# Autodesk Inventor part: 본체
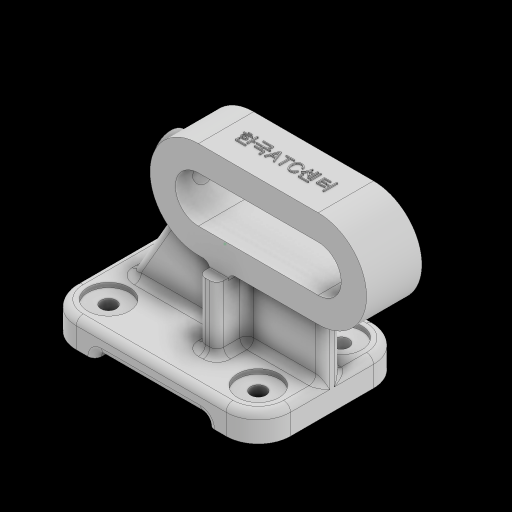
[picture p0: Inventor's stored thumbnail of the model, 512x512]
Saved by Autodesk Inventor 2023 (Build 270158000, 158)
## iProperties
Created: 2025-01
Part Number: 본체
Material: 일반
Document SubType Name: Modeling
Designer: 강의실01
Density: 1 g/cm^3
Appearance: 기본값
Author: 강의실01
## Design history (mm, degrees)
sketch "스케치1"
  geometry: L1 (46.5, -32)-(-46.5, -32); L2 (-46.5, -32)-(-46.5, 32); L3 (-46.5, 32)-(46.5, 32); L4 (46.5, 32)-(46.5, -32); L5 (46.5, -32)-(-46.5, 32); L6 (-46.5, -32)-(46.5, 32); 1 further point
  constraints: 12 end point, 2 midpoint, 2 parallel, 1 horizontal, 1 perpendicular
  dimensions: "d0" = 93 distance of L2.end L3.end; "d1" = 64 distance of L1.end L2.end
extrude "돌출1" new body sketch "스케치1" distance "d2" = 12; taper "d3" = 0 deg
fillet "모깎기1" dims "d4" = 14
sketch "스케치2"
  geometry: L1 (-37.5, -4)-(46.5, -4); L2 (46.5, -4)-(46.5, 4); L3 (46.5, 4)-(-37.5, 4); L4 (-37.5, 4)-(-37.5, -4); L5 (0, 0)-(46.5, 0); L6 (46.5, -18)-(46.5, 18) reference; L7 (-46.5, 18)-(-46.5, -18) reference
  constraints: 10 end point, 2 parallel, 1 collinear, 1 horizontal, 1 midpoint, 1 perpendicular, 1 other
  dimensions: "d5" = 8 distance of L1.end L2.end; "d6" = 9 distance between parallel lines of L4 L7
extrude "돌출2" join sketch "스케치2" distance "d7" = 51; taper "d8" = 0 deg
sketch "스케치3"
  geometry: L1 (46.5, 18)-(46.5, 4) reference; L2 (-37.5, 4)-(46.5, 4) reference; L3 (-37.5, -4)-(-37.5, 4) reference; L4 (46.5, -4)-(-37.5, -4) reference; L5 (46.5, -4)-(46.5, -18) reference; L6 (32.5, -32)-(-32.5, -32) reference; L7 (-46.5, -18)-(-46.5, 18) reference; L8 (-32.5, 32)-(32.5, 32) reference; L9 (46.5, 4)-(46.5, -4) reference; L10 (5.5, 17)-(13.5, 17); L11 (13.5, 17)-(13.5, -17); L12 (13.5, -17)-(5.5, -17); L13 (5.5, -17)-(5.5, 17); L14 (0, 0)-(46.5, 0); A1 r 14 centre (32.5, 18) between (46.5, 18) and (32.5, 32) reference; A2 r 14 centre (32.5, -18) between (32.5, -32) and (46.5, -18) reference; A3 r 14 centre (-32.5, -18) between (-46.5, -18) and (-32.5, -32) reference; A4 r 14 centre (-32.5, 18) between (-32.5, 32) and (-46.5, 18) reference
  constraints: 10 end point, 2 parallel, 1 horizontal, 1 midpoint, 1 perpendicular, 1 other
  dimensions: "d9" = 8 distance of L10.start L10.end; "d10" = 33 distance between parallel lines of L9 L11; "d11" = 34 distance of L10.end L11.end
extrude "돌출3" join sketch "스케치3" distance "d12" = 51; taper "d13" = 0 deg
feature "면 기울기1" dims angle "d14" = 30 deg
sketch "스케치4"
  geometry: L1 (-46.5, 12)-(-37.5, 12) reference; L2 (-37.5, 12)-(-8.055, 63) reference; L3 (-8.055, 63)-(46.5, 63) reference; L4 (46.5, 63)-(46.5, 0) reference; L5 (46.5, 0)-(-46.5, 0) reference; L6 (-46.5, 0)-(-46.5, 12) reference; L7 (-24.5, 0)-(24.5, 0); L8 (24.5, 0)-(24.5, 3); L9 (24.5, 3)-(-24.5, 3); L10 (-24.5, 3)-(-24.5, 0); 3 further points
  constraints: 8 end point, 2 parallel, 1 collinear, 1 horizontal, 1 perpendicular
  dimensions: "d15" = 22 distance between parallel lines of L10 L6; "d16" = 22 distance between parallel lines of L4 L8; "d17" = 3 distance between parallel lines of L5 L9
extrude "돌출4" cut sketch "스케치4" extent not by distance; stored distance "d18" = 32; taper "d19" = 0 deg
sketch "스케치5"
  geometry: L1 (-46.5, 12)-(-37.5, 12) reference; L2 (-37.5, 12)-(-8.055, 63) reference; L3 (-8.055, 63)-(46.5, 63) reference; L4 (46.5, 63)-(46.5, 0) reference; L5 (46.5, 0)-(24.5, 0) reference; L6 (24.5, 0)-(24.5, 3) reference; L7 (24.5, 3)-(-24.5, 3) reference; L8 (-24.5, 3)-(-24.5, 0) reference; L9 (-24.5, 0)-(-46.5, 0) reference; L10 (-46.5, 0)-(-46.5, 12) reference; L11 (0.5, 63)-(52.5, 63); L12 (0.5, 84)-(52.5, 84); L13 (52.5, 42)-(0.5, 42); A1 r 21 centre (0.5, 63) between (0.5, 84) and (0.5, 42); A2 r 21 centre (52.5, 63) between (52.5, 42) and (52.5, 84); 3 further points
  constraints: 8 end point, 5 point on circle, 4 tangent, 2 centre point, 1 horizontal, 1 midpoint, 1 parallel
  dimensions: "d20" = 21 radius of A2; "d21" = 63 distance from line of L5 L11.end; "d22" = 120 distance from line of point (73.5, 63) L10; "d23" = 52 distance of L11.end L11.start
extrude "돌출5" join sketch "스케치5" stored distance "d24" = 24; taper "d25" = 0 deg
node "작업 평면1"
sketch "스케치6"
  geometry: 1 further point
sketch "스케치7"
  geometry: L1 (5, 16)-(5, 29) reference; L2 (5, 29)-(13, 29) reference; L3 (13, 29)-(13, 16) reference; L4 (13, 16)-(46, 16) reference; L5 (46, 16)-(46, 8) reference; L6 (46, 8)-(13, 8) reference; L7 (13, 8)-(13, -5) reference; L8 (13, -5)-(5, -5) reference; L9 (5, -5)-(5, 8) reference; L10 (5, 8)-(-21.834, 8) reference; L11 (-21.834, 8)-(-21.834, 16) reference; L12 (-21.834, 16)-(5, 16) reference; L13 (5, 29)-(13, 29) reference; L14 (13, 29)-(13, 16) reference; L15 (5, 29)-(13, 29); L16 (13, 29)-(13, 24); L17 (13, 24)-(5, 24); L18 (5, 24)-(5, 29); L19 (13, 8)-(13, -5) reference; L20 (5, -5)-(13, -5); L21 (13, -5)-(13, 0); L22 (13, 0)-(5, 0); L23 (5, 0)-(5, -5); 5 further points
  constraints: 16 end point, 4 parallel, 2 horizontal, 2 perpendicular, 2 point on line
  dimensions: "d27" = 5 distance between parallel lines of L17 L2; "d28" = 5 distance between parallel lines of L8 L22
extrude "돌출6" cut sketch "스케치7" extent not by distance; stored distance "d29" = 0; taper "d30" = 0 deg
sketch "스케치8"
  geometry: L1 (-46.5, 12)-(-37.5, 12) reference; L2 (-37.5, 12)-(-15.741, 49.687) reference; L3 (0.5, 84)-(52.5, 84) reference; L4 (52.5, 42)-(46.5, 42) reference; L5 (46.5, 42)-(46.5, 0) reference; L6 (46.5, 0)-(24.5, 0) reference; L7 (24.5, 0)-(24.5, 3) reference; L8 (24.5, 3)-(-24.5, 3) reference; L9 (-24.5, 3)-(-24.5, 0) reference; L10 (-24.5, 0)-(-46.5, 0) reference; L11 (-46.5, 0)-(-46.5, 12) reference; L12 (0.5, 63)-(52.5, 63); L13 (0.5, 73)-(52.5, 73); L14 (52.5, 53)-(0.5, 53); A1 r 21 centre (0.5, 63) between (0.5, 84) and (-15.741, 49.687) reference; A2 r 21 centre (52.5, 63) between (52.5, 42) and (52.5, 84) reference; A3 r 21 centre (0.5, 63) between (0.5, 84) and (0.5, 42) reference; A4 r 10 centre (0.5, 63) between (0.5, 73) and (0.5, 53); A5 r 10 centre (52.5, 63) between (52.5, 53) and (52.5, 73); 2 further points
  constraints: 8 end point, 4 point on circle, 4 tangent, 2 centre point, 1 horizontal, 1 midpoint, 1 parallel
  dimensions: "d31" = 10 radius of A5
extrude "돌출7" cut sketch "스케치8" extent not by distance; stored distance "d32" = 0; taper "d33" = 0 deg
sketch "스케치9"
  geometry: A1 r 14 centre (-32.5, 18) between (-32.5, 32) and (-46.5, 18) reference; A2 r 14 centre (32.5, 18) between (46.5, 18) and (32.5, 32) reference; A3 r 14 centre (-32.5, -18) between (-46.5, -18) and (-32.5, -32) reference; A4 r 14 centre (32.5, -18) between (32.5, -32) and (46.5, -18) reference; 5 further points
  constraints: 4 coincident
hole "구멍1" sketch "스케치9" at (-32.5, -18), (32.5, -18), (-32.5, 18), (32.5, 18) diameter "d34" = 6.6; stored, may be unused: countersink angle "d38" = 90 deg, drill point angle "d40" = 118 deg; dims "d35" = 8, "d36" = 18, "d37" = 2, "d39" = 10
node "작업 평면3"
  node "작업 평면2"
sketch "스케치10"
  geometry: L1 (-53, -18)-(-53, 18) reference; L2 (31, -12)-(31, 12) reference; C1 r 8 at (10, 0); 2 further points
  constraints: 1 centre point, 1 horizontal alignment, 1 midpoint
  dimensions: "d42" = 16 diameter of C1; "d43" = 63 distance from line of L1 C1.centre
extrude "돌출8" join sketch "스케치10" stored distance "d44" = 10; taper "d45" = 0 deg
sketch "스케치11"
  geometry: C1 r 4.5 at (0, 0); 1 further point
  constraints: 1 centre point
  dimensions: "d46" = 9 diameter of C1
extrude "돌출9" cut sketch "스케치11" stored distance "d47" = 10; taper "d48" = 0 deg
fillet "모깎기2" dims "d49" = 3
fillet "모깎기3" dims "d50" = 3
fillet "모깎기4" dims "d51" = 3
fillet "모깎기5" dims "d52" = 3
fillet "모깎기6" dims "d53" = 3
fillet "모깎기7" dims "d54" = 3
fillet "모깎기8" dims "d55" = 3
sketch "스케치12"
  geometry: L1 (52, 24)-(52, 0) reference; 2 further points
  constraints: 1 horizontal alignment, 1 other
  dimensions: "d56" = 26 distance from line of L1 point (26, 12)
feature "엠보싱1" sketch "스케치12" dims "d0" = 93, "d1" = 64, "d6" = 9, "d57" = 0.5, "d58" = 0
node "솔리드1"
node "절단 모서리 투영1"
node "절단 모서리 투영2"
node "절단 모서리 투영3"
node "절단 모서리 투영4"
node "절단 모서리 투영5"
feature "A9D066F2-1C7D-4E18-AEED-F7BC21143FA4" dims "d34" = 6.6, "d35" = 8, "d36" = 18, "d37" = 2, "d38" = 90 deg, "d39" = 10, "d40" = 118 deg
other parameters: "d26" = -44, "d41" = -24
